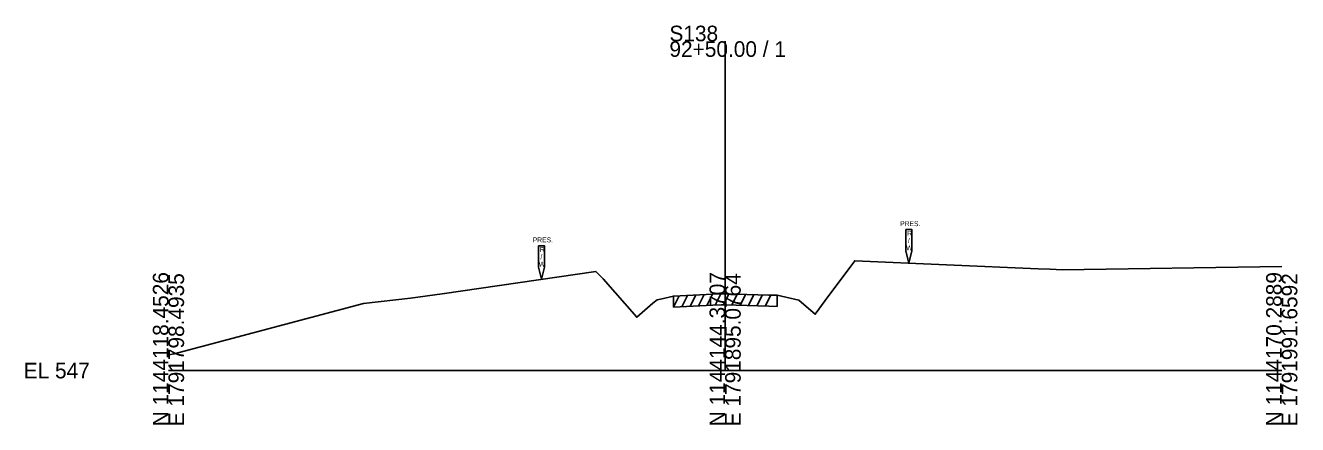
# Model space of a CAD drawing. Extents: x -26 to 1203, y -10 to 19606.
# Drawn here: x 974.3 to 1202.8, y 4990.3 to 5062 of the extents above; entities that cross this region are included whole.
import ezdxf

# ---------------------------------------------------------------- set-up
doc = ezdxf.new("R2010")
doc.units = 0
for name, color, linetype in [('RD_EX_Driveway', 7, 'Continuous'), ('RD_GPK_XS_Cell', 7, 'Continuous'), ('RD_XS_ExGround', 7, 'Continuous'), ('RD_XS_ExPaveRet', 7, 'Continuous'), ('RD_XS_ExRW', 7, 'Continuous')]:
    doc.layers.add(name, color=color, linetype=linetype)

msp = doc.modelspace()

# ---------------------------------------------------------------- linework, layer by layer
at = {"layer": 'RD_GPK_XS_Cell'}
for p, q in [((1100, 5000), (1100, 5059.14)), ((1000, 5000), (1100, 5000)), ((1100, 5000), (1200, 5000))]:
    msp.add_line(p, q, dxfattribs=at)
at = {"layer": 'RD_XS_ExGround'}
msp.add_lwpolyline([(1000, 5002.8), (1001.05, 5003.03), (1035.01, 5012.06), (1043.49, 5012.98), (1049.16, 5013.8), (1076.8, 5017.81), (1078.1, 5016.48), (1084.12, 5009.59), (1086.99, 5012.09), (1087.78, 5012.72), (1088.4, 5012.85), (1090.7, 5013.38), (1097.8, 5013.74), (1099.29, 5013.79), (1100, 5013.78), (1107.84, 5013.56), (1109.36, 5013.52), (1113.26, 5012.65), (1114.99, 5011.15), (1116.19, 5010.13), (1117.99, 5012.56), (1123.29, 5019.71), (1156.24, 5018.3), (1158.4, 5018.21), (1160.58, 5018.1), (1200, 5018.69)], dxfattribs=at)
at = {"layer": 'RD_XS_ExPaveRet'}
for p, q in [((1090.7, 5011.38), (1091.73, 5013.43)), ((1090.7, 5011.38), (1090.7, 5013.38)), ((1090.7, 5011.38), (1097.8, 5011.74)), ((1092.2, 5011.45), (1093.23, 5013.5)), ((1093.7, 5011.53), (1094.73, 5013.58)), ((1095.2, 5011.6), (1096.23, 5013.66)), ((1096.7, 5011.68), (1097.73, 5013.73)), ((1097.8, 5011.74), (1099.29, 5011.79)), ((1098.2, 5011.75), (1099.22, 5013.79)), ((1099.29, 5011.79), (1100, 5011.78)), ((1099.7, 5011.78), (1100.69, 5013.76)), ((1100, 5011.78), (1107.84, 5011.56)), ((1101.2, 5011.74), (1102.19, 5013.72)), ((1102.7, 5011.7), (1103.69, 5013.68)), ((1104.2, 5011.66), (1105.19, 5013.64)), ((1105.7, 5011.62), (1106.69, 5013.6)), ((1107.2, 5011.58), (1108.19, 5013.55)), ((1109.36, 5013.52), (1109.36, 5011.52)), ((1107.84, 5011.56), (1109.36, 5011.52))]:
    msp.add_line(p, q, dxfattribs=at)
at = {"layer": 'RD_XS_ExRW'}
for points in [[(1132.45, 5025.31), (1133.55, 5025.31), (1133.55, 5021.49), (1133, 5019.3), (1132.45, 5021.49)], [(1066.45, 5022.41), (1067.55, 5022.41), (1067.55, 5018.58), (1067, 5016.39), (1066.45, 5018.58)]]:
    msp.add_lwpolyline(points, close=True, dxfattribs=at)

# ---------------------------------------------------------------- texts
at = {"layer": 'RD_EX_Driveway'}
msp.add_text('553.89', height=0.0975, rotation=90, dxfattribs=at).set_placement((1100.1, 5013.78))
at = {"layer": 'RD_GPK_XS_Cell'}
for s, p in [('S138', (1090, 5059.14)), ('92+50.00 / 1', (1090, 5056.34)), ('EL 547', (974, 4998.6))]:
    msp.add_text(s, height=2.8, dxfattribs=at).set_placement(p)
for s, p in [('N 1144118.4526', (1000, 4990)), ('E 1791798.4935', (1002.8, 4990)), ('N 1144144.3707', (1100, 4990)), ('E 1791895.0764', (1102.8, 4990)), ('N 1144170.2889', (1200, 4990)), ('E 1791991.6592', (1202.8, 4990))]:
    msp.add_text(s, height=2.8, rotation=90, dxfattribs=at).set_placement(p)
at = {"layer": 'RD_XS_ExRW'}
for s, p in [('PRES.', (1131.45, 5025.94)), ('PRES.', (1065.45, 5023.03)), ('R', (1132.71, 5024.22)), ('/', (1132.83, 5022.91)), ('R', (1066.71, 5021.32)), ('/', (1066.83, 5020)), ('W', (1132.53, 5021.6)), ('W', (1066.53, 5018.69))]:
    msp.add_text(s, height=0.875, dxfattribs=at).set_placement(p)

doc.saveas('drawing.dxf')
